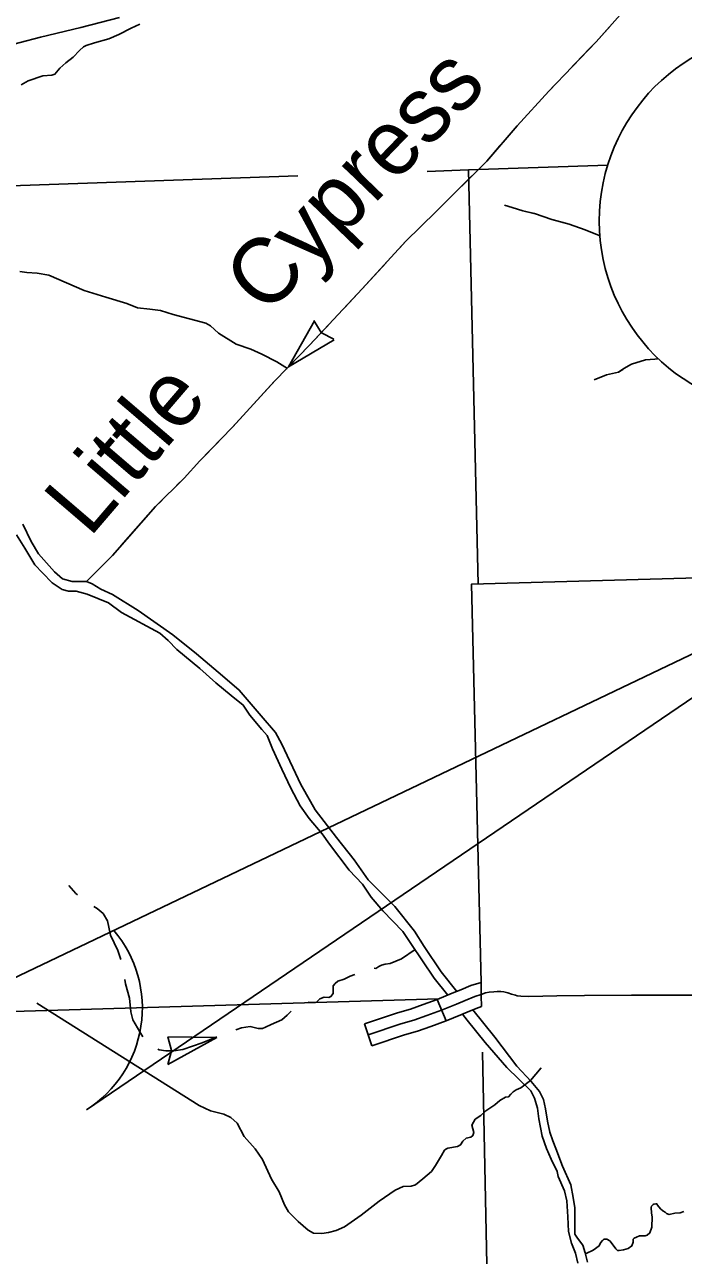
# Model space of a CAD drawing. Extents: x -117616 to 64730, y 54117 to 789866.
# Drawn here: x 62825.8 to 62911, y 54599.6 to 54758.9 of the extents above; entities that cross this region are included whole.
import ezdxf

# ---------------------------------------------------------------- set-up
doc = ezdxf.new("R2010")
doc.units = 0
for name, color, linetype in [('32', 7, 'Continuous'), ('34', 7, 'Continuous'), ('35', 7, 'Continuous'), ('4', 7, 'Continuous'), ('43', 7, 'Continuous'), ('45', 7, 'Continuous'), ('5', 7, 'Continuous'), ('6', 7, 'Continuous'), ('R_Dimension', 7, 'Continuous'), ('R_Draft', 7, 'Continuous')]:
    doc.layers.add(name, color=color, linetype=linetype)

msp = doc.modelspace()

# ---------------------------------------------------------------- linework, layer by layer
at = {"layer": '32'}
msp.add_line((62880.3, 54629.99), (62879.14, 54632.75), dxfattribs=at)
for points in [[(62879.14, 54632.75), (62881.07, 54633.56), (62882.19, 54634.01), (62883.52, 54634.55), (62884.82, 54634.96), (62884.86, 54633.23), (62884.89, 54631.84)], [(62879.72, 54631.37), (62881.64, 54632.17), (62882.76, 54632.62), (62884.02, 54633.14), (62884.86, 54633.4)], [(62880.3, 54629.99), (62882.21, 54630.79), (62883.32, 54631.24), (62884.53, 54631.73), (62884.89, 54631.84)]]:
    msp.add_lwpolyline(points, dxfattribs=at)
at = {"layer": '34'}
for points in [[(62838.05, 54759.85), (62833.03, 54758.56), (62827.82, 54757.34), (62822.5, 54755.93)], [(62930.06, 54633.42), (62927.12, 54633.4), (62920.82, 54633.36), (62915.44, 54633.33), (62909.86, 54633.33), (62904.28, 54633.31), (62898.21, 54633.27), (62894.64, 54633.21), (62891, 54633.16), (62889.99, 54633.18), (62889.52, 54633.24), (62889.27, 54633.3), (62888.76, 54633.46), (62888.29, 54633.63), (62887.77, 54633.73), (62887.38, 54633.79), (62886.9, 54633.81), (62886.46, 54633.75), (62885.89, 54633.69), (62885.38, 54633.6), (62884.86, 54633.4)]]:
    msp.add_lwpolyline(points, dxfattribs=at)
at = {"layer": '35'}
for points in [[(62825.31, 54751.15), (62826.23, 54751.69), (62828.12, 54752.32), (62829.28, 54752.39), (62829.69, 54752.53), (62830.34, 54753.31), (62831.12, 54753.99), (62832.06, 54754.74), (62832.88, 54755.58), (62833.37, 54756.09), (62833.75, 54756.26), (62834.82, 54756.6), (62836.65, 54757.11), (62837.94, 54757.67), (62839.56, 54758.47), (62840.69, 54759)], [(62825.13, 54726.98), (62826.04, 54726.85), (62827.39, 54726.79), (62828.9, 54726.52), (62833.49, 54724.52), (62836.26, 54723.65), (62838.99, 54722.84), (62840.36, 54722.3), (62841.96, 54722.11), (62843.34, 54721.96), (62844.97, 54721.42), (62849.2, 54720.29), (62849.8, 54719.95), (62850.87, 54719.01), (62853.12, 54717.59), (62855.04, 54716.94), (62856.45, 54716.28), (62858.39, 54715.3), (62859.8, 54714.43)], [(62825.54, 54694.28), (62826.63, 54692.06), (62827.56, 54690.45), (62829.64, 54688.11), (62830.67, 54687.22), (62831.9, 54686.88), (62833.16, 54686.85), (62833.78, 54686.88), (62834.49, 54686.58), (62835.63, 54685.89), (62837.15, 54685.17), (62840.46, 54683.1), (62844.94, 54679.94), (62848.02, 54677.48), (62851.38, 54674.64), (62853.55, 54672.81), (62856.38, 54669.48), (62858.23, 54667.31), (62859.04, 54665.81), (62861.51, 54660.6), (62862.77, 54658.38), (62863.36, 54657.32), (62866.14, 54653.72), (62868.39, 54650.85), (62870.23, 54648.26), (62873.69, 54644.81), (62876.22, 54641.58), (62877.46, 54639.63), (62879.65, 54636.32), (62881.7, 54633.81)], [(62824.71, 54692.89), (62825.8, 54691.19), (62827.11, 54689.01), (62828.08, 54687.97), (62829.32, 54686.68), (62830.61, 54685.84), (62831.45, 54685.61), (62832.44, 54685.63), (62833.86, 54685.23), (62836.62, 54684.11), (62838.32, 54682.87), (62843.26, 54680.18), (62844.35, 54679.24), (62845.47, 54678.05), (62848.46, 54675.59), (62850.51, 54673.76), (62852.51, 54672.09), (62854.06, 54670.87), (62854.9, 54669.55), (62856.44, 54667.7), (62857.15, 54666.91), (62857.84, 54665.18), (62859.05, 54662.57), (62860.22, 54660.13), (62861.41, 54657.83), (62862.6, 54656.2), (62864.25, 54654.2), (62865.21, 54652.85), (62867.75, 54649.48), (62869.47, 54647.7), (62870.59, 54645.98), (62872.11, 54644.25), (62874.72, 54641.54), (62875.73, 54639.99), (62878.78, 54635.5), (62880.52, 54633.33)], [(62883.78, 54631.42), (62886.6, 54627.88), (62889.44, 54624.11), (62891.29, 54622.16), (62892.37, 54620.83), (62892.91, 54619.79), (62893.16, 54618.6), (62893.41, 54617), (62893.73, 54615.59), (62894.1, 54614.44), (62894.49, 54613.47), (62895.35, 54611.18), (62896.46, 54608.76), (62896.73, 54607.11), (62896.96, 54605.77), (62896.96, 54603.53), (62896.98, 54602.39), (62897.3, 54601.85), (62897.99, 54600.96), (62898.31, 54599.95), (62898.58, 54598.77)], [(62882.43, 54630.86), (62883.01, 54630.07), (62885.37, 54627.2), (62888.18, 54623.95), (62891.27, 54620.93), (62891.73, 54619.99), (62892.14, 54618.7), (62892.31, 54617.31), (62892.74, 54615.07), (62893.28, 54613.45), (62893.88, 54612.08), (62894.67, 54610.48), (62894.82, 54609.85), (62895.61, 54607.99), (62895.94, 54606.7), (62896.04, 54604.64), (62896.12, 54602.72), (62896.52, 54601.22), (62897.03, 54599.92), (62897.33, 54598.61)], [(62898.42, 54599.87), (62899.33, 54600.29), (62900.1, 54600.88), (62900.28, 54601.26), (62900.52, 54601.56), (62900.67, 54601.68), (62900.78, 54601.71), (62901.08, 54601.71), (62901.49, 54601.5), (62901.91, 54600.94), (62902.26, 54600.49), (62902.5, 54600.26), (62902.68, 54600.26), (62903.27, 54600.37), (62903.86, 54600.52), (62904.33, 54600.85), (62904.51, 54601.35), (62904.51, 54601.74), (62904.63, 54601.85), (62904.95, 54602), (62905.31, 54602.15), (62905.57, 54602.15), (62905.84, 54602.15), (62906.08, 54602.15), (62906.31, 54602.24), (62906.67, 54602.54), (62906.93, 54603.28), (62906.96, 54604.61), (62906.88, 54605.08), (62906.85, 54605.82), (62906.88, 54606), (62907.11, 54606.21), (62907.2, 54606.26), (62907.44, 54606.29), (62907.59, 54606.29), (62907.64, 54606.15), (62908.03, 54605.67), (62908.35, 54605.38), (62908.65, 54605.23), (62908.83, 54605.05), (62909.15, 54604.93), (62909.89, 54605.08), (62910.6, 54605.14), (62911.08, 54605.32)]]:
    msp.add_lwpolyline(points, dxfattribs=at)
at = {"layer": '4'}
msp.add_lwpolyline([(62883.2, 54740.13), (62884.45, 54686.52)], dxfattribs=at)
at = {"layer": '43'}
for p, q in [((62859.9, 54714.64), (62863.26, 54720.62)), ((62863.19, 54720.64), (62864.16, 54719.09)), ((62865.79, 54718.21), (62864.18, 54719.07)), ((62859.9, 54714.64), (62865.81, 54718.14)), ((62844.29, 54627.9), (62844.76, 54626.14)), ((62850.65, 54627.82), (62844.29, 54627.9)), ((62850.65, 54627.82), (62844.29, 54624.35)), ((62844.29, 54624.35), (62844.76, 54626.12))]:
    msp.add_line(p, q, dxfattribs=at)
for points in [[(62903.18, 54760.59), (62899.7, 54756.73), (62893.59, 54750.35), (62889.52, 54745.85), (62885.56, 54741.29), (62879.03, 54734.75), (62875.06, 54730.89), (62869.44, 54724.73), (62862.64, 54717.44), (62858.19, 54712.89), (62852.62, 54706.78), (62848.45, 54702.49), (62846.41, 54700.24), (62842.72, 54696.59), (62837.15, 54690.21), (62833.78, 54686.88)], [(62901.56, 54758.79), (62899.7, 54756.73), (62898.88, 54755.88)], [(62898.88, 54755.88), (62896.14, 54753.01)], [(62894.32, 54751.11), (62893.59, 54750.35), (62889.52, 54745.85), (62889, 54745.24)], [(62887.26, 54743.25), (62885.56, 54741.29), (62881.8, 54737.53)], [(62879.93, 54735.66), (62879.03, 54734.75), (62875.06, 54730.89), (62874.32, 54730.07)], [(62887.84, 54735.59), (62888.84, 54735.28), (62890.22, 54734.85), (62891.65, 54734.5)], [(62887.84, 54735.59), (62888.84, 54735.28), (62890.22, 54734.85), (62891.74, 54734.48), (62893.98, 54733.72), (62896.22, 54733.11), (62898.28, 54732.38), (62899.48, 54731.91), (62900.23, 54731.6)], [(62894.15, 54733.68), (62896.22, 54733.11), (62898.28, 54732.38), (62899.48, 54731.91), (62900.23, 54731.6)], [(62872.54, 54728.12), (62869.44, 54724.73), (62867.17, 54722.3)], [(62865.37, 54720.37), (62862.64, 54717.44), (62859.9, 54714.64)], [(62899.46, 54712.98), (62901.04, 54713.62), (62902.59, 54713.97), (62903.18, 54714.33), (62903.62, 54714.61), (62904.29, 54715.01), (62906.11, 54715.56), (62907.3, 54715.64), (62907.62, 54715.68), (62907.73, 54715.78)], [(62905.55, 54715.39), (62906.11, 54715.56), (62907.3, 54715.64), (62907.62, 54715.68), (62907.73, 54715.78)], [(62899.46, 54712.98), (62901.04, 54713.62), (62902.59, 54713.97), (62903.16, 54714.32)], [(62858.06, 54712.74), (62855.4, 54709.82)], [(62855.4, 54709.82), (62852.73, 54706.89)], [(62850.89, 54705), (62848.45, 54702.49), (62846.41, 54700.24), (62845.43, 54699.27)], [(62843.55, 54697.41), (62842.72, 54696.59), (62838.28, 54691.51)], [(62836.49, 54689.56), (62833.78, 54686.88)], [(62831.47, 54647.52), (62832.4, 54646.49), (62832.6, 54646.31)], [(62834.73, 54644.78), (62835.16, 54644.53), (62835.93, 54643.89), (62836.5, 54642.92), (62836.89, 54641.06), (62837.85, 54639.1), (62838.23, 54637.95)], [(62870.99, 54636.8), (62871.22, 54636.76), (62871.6, 54637.02), (62871.96, 54637.21), (62872.4, 54637.34), (62873.08, 54637.43), (62874.52, 54638.01), (62876.32, 54639.23)], [(62862.44, 54632.43), (62863.13, 54632.36), (62863.55, 54632.42), (62863.97, 54632.84), (62864.51, 54633.06), (62865.12, 54633.03), (62865.41, 54633.16), (62865.67, 54633.51), (62865.67, 54634), (62865.67, 54634.51), (62865.96, 54634.83), (62866.28, 54635.12), (62867.11, 54635.38), (62867.91, 54635.79), (62868.5, 54636)], [(62838.72, 54635.36), (62838.81, 54634.77), (62839.33, 54632.94), (62839.52, 54631.14), (62839.78, 54630.11), (62840.67, 54628.57), (62841.08, 54627.92)], [(62827.37, 54632.26), (62848.37, 54619.05), (62849.8, 54618.35), (62851.56, 54617.91), (62852.47, 54617.5), (62853.29, 54616.73), (62854.16, 54615.04), (62855.62, 54613.41), (62856.53, 54612.06), (62857.72, 54609.5), (62858.71, 54607.87), (62859.38, 54606.19), (62859.9, 54605.27), (62861.18, 54604.03), (62862.44, 54602.88), (62863.14, 54602.51), (62864.22, 54602.48), (62865.09, 54602.59), (62866.08, 54602.87), (62867.14, 54603.33), (62869.32, 54604.84), (62871.65, 54606.63), (62873.71, 54608.08), (62874.75, 54608.54), (62875.8, 54608.6), (62876.35, 54608.75), (62877.3, 54609.55), (62878.43, 54610.5), (62878.95, 54611.25), (62879.69, 54612.56), (62880.09, 54613.24), (62880.28, 54613.39), (62880.54, 54613.53), (62881.78, 54613.74), (62882.17, 54613.92), (62882.46, 54614.43), (62882.92, 54614.8), (62883.52, 54614.93), (62883.76, 54615.13), (62883.91, 54615.54), (62883.78, 54616.01), (62883.64, 54616.5), (62883.83, 54616.89), (62884.07, 54617.25), (62884.8, 54617.73), (62885.46, 54618.34), (62886.6, 54619.13), (62887.25, 54619.68), (62887.99, 54620.12), (62888.38, 54620.16), (62888.68, 54620.52), (62888.97, 54620.8), (62889.37, 54621.04), (62889.99, 54621.32), (62891.22, 54622.26), (62892.62, 54623.92)], [(62856.94, 54629.19), (62857.68, 54629.53), (62859.03, 54630.14), (62859.73, 54630.72), (62860.26, 54631.25)], [(62843.02, 54626.31), (62843.18, 54626.26), (62844.04, 54626.13), (62845.07, 54626.13), (62846.22, 54626.29), (62848.73, 54627.16), (62850.62, 54627.91)], [(62853.1, 54628.82), (62853.83, 54629.08), (62854.95, 54629.24), (62855.98, 54629.02), (62856.56, 54629.02), (62856.94, 54629.19)]]:
    msp.add_lwpolyline(points, dxfattribs=at)
at = {"layer": '45'}
msp.add_line((62870.71, 54626.74), (62869.75, 54629.59), dxfattribs=at)
for points in [[(62869.75, 54629.59), (62874, 54631.02), (62875.68, 54631.52), (62877.32, 54632.09), (62879.14, 54632.75)], [(62870.23, 54628.17), (62874.45, 54629.59), (62876.14, 54630.09), (62877.82, 54630.68), (62879.72, 54631.37)], [(62870.71, 54626.74), (62874.91, 54628.16), (62876.61, 54628.66), (62878.33, 54629.27), (62880.3, 54629.99)]]:
    msp.add_lwpolyline(points, dxfattribs=at)
at = {"layer": '5'}
msp.add_lwpolyline([(62879.37, 54632.84), (62779.29, 54629.85)], dxfattribs=at)
at = {"layer": '6'}
for points in [[(62800.41, 54737.32), (62805.4, 54737.43), (62861.12, 54739.36)], [(62877.87, 54739.94), (62883.2, 54740.13), (62901.24, 54740.77)], [(62929.84, 54687.83), (62883.57, 54686.5), (62884.82, 54634.96)], [(62885.01, 54625.92), (62885.61, 54596.34), (62889.23, 54529.4)]]:
    msp.add_lwpolyline(points, dxfattribs=at)
at = {"layer": 'R_Dimension'}
msp.add_line((62833.79, 54618.49), (62940.1, 54690.83), dxfattribs=at)
msp.add_lwpolyline([(62940.1, 54690.83), (62215.14, 54344.27), (61753.25, 54344.27)], dxfattribs=at)
msp.add_arc((62825.41, 54631.64), 15.59, 302.5041, 40.1655, dxfattribs=at)
at = {"layer": 'R_Draft'}
msp.add_circle((62924.72, 54733.52), 24.6, dxfattribs=at)

# ---------------------------------------------------------------- texts
at = {"layer": '43'}
for s, rotation, p in [('Cypress', 46.0391, (62857, 54721.13)), ('Little', 49.4235, (62834.16, 54692.41))]:
    msp.add_text(s, height=8.448, rotation=rotation, dxfattribs=at).set_placement(p)

doc.saveas('drawing.dxf')
